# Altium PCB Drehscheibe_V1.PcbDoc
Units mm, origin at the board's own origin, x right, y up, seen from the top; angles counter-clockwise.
Board outline 100 x 80 mm, 2 copper layers (Top Layer, Bottom Layer); 75 components, 66 nets, 301 pads, 41 vias.
Unrouted connection lines stored in the file: 1.
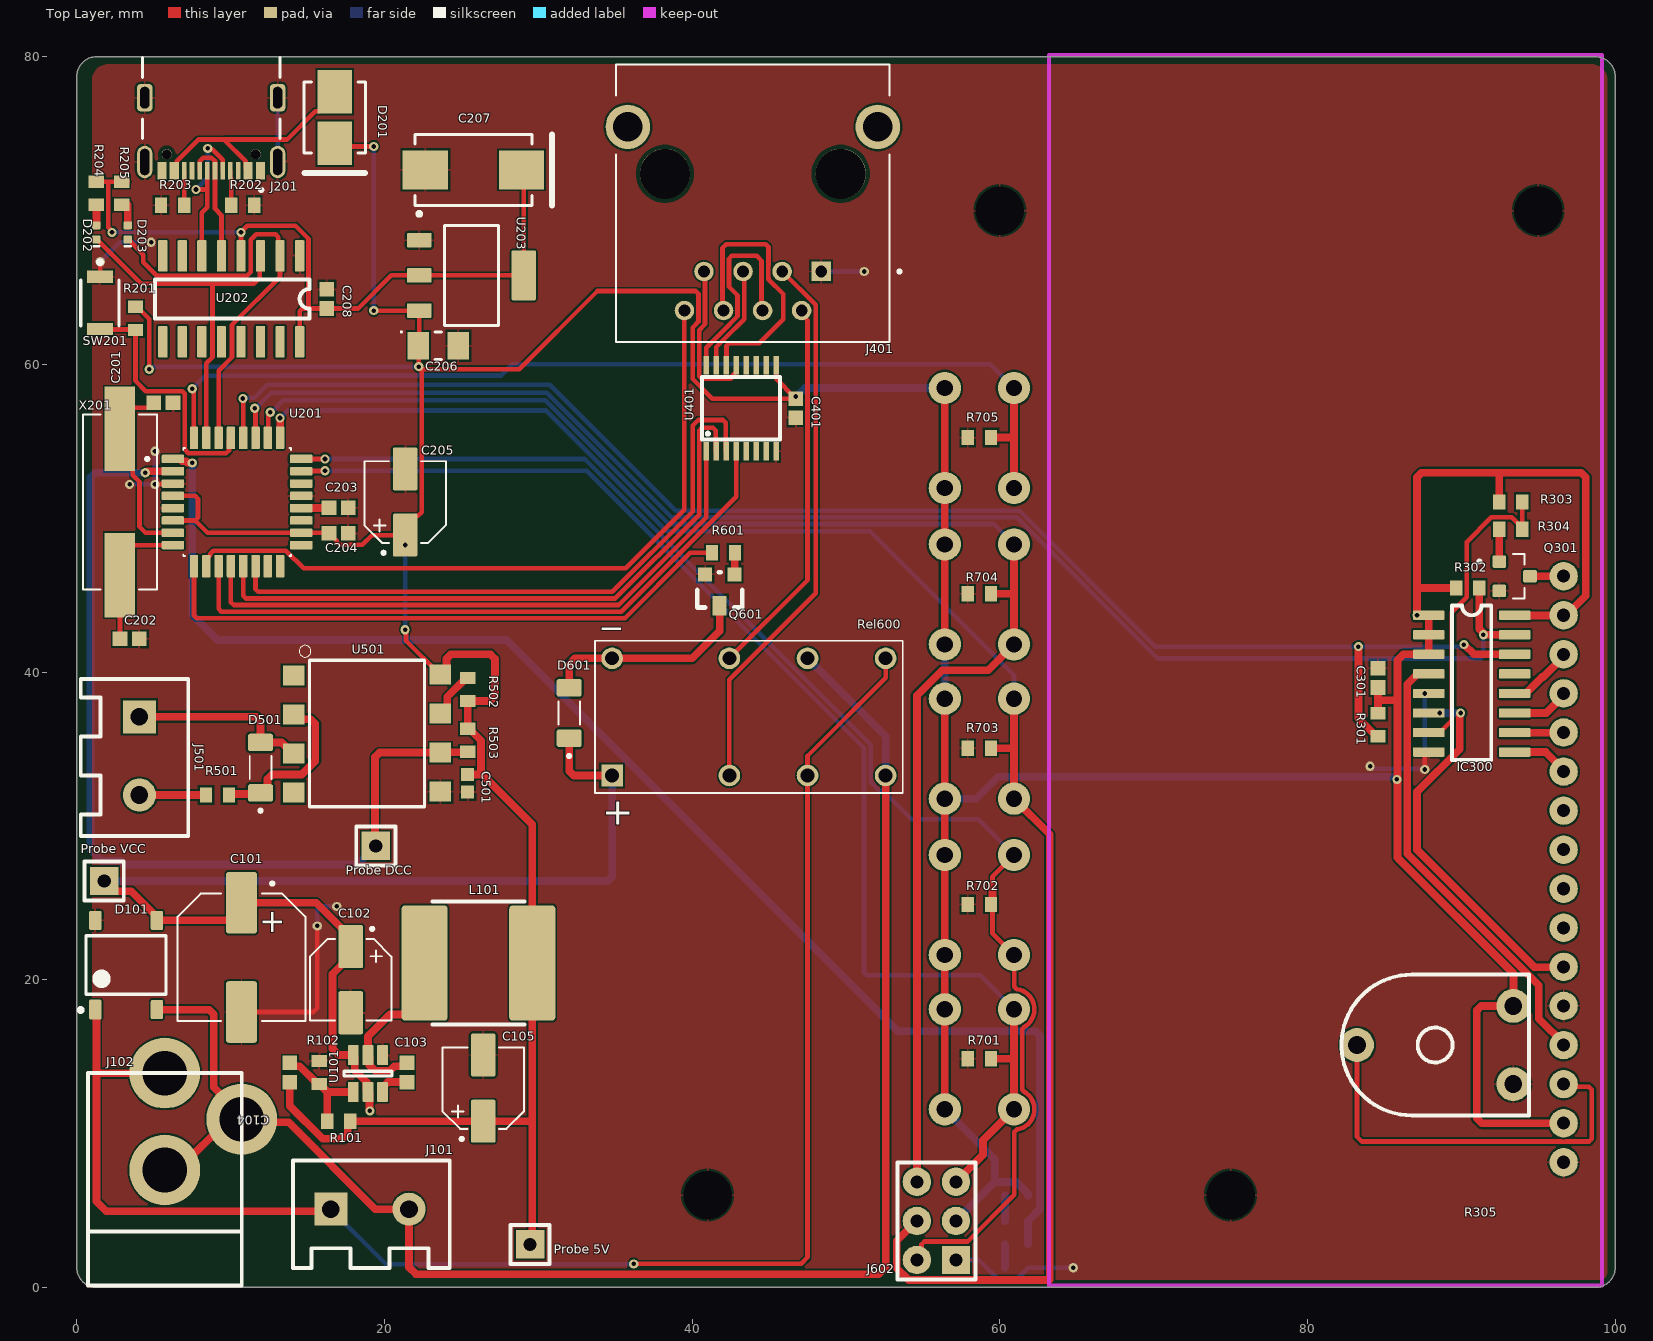
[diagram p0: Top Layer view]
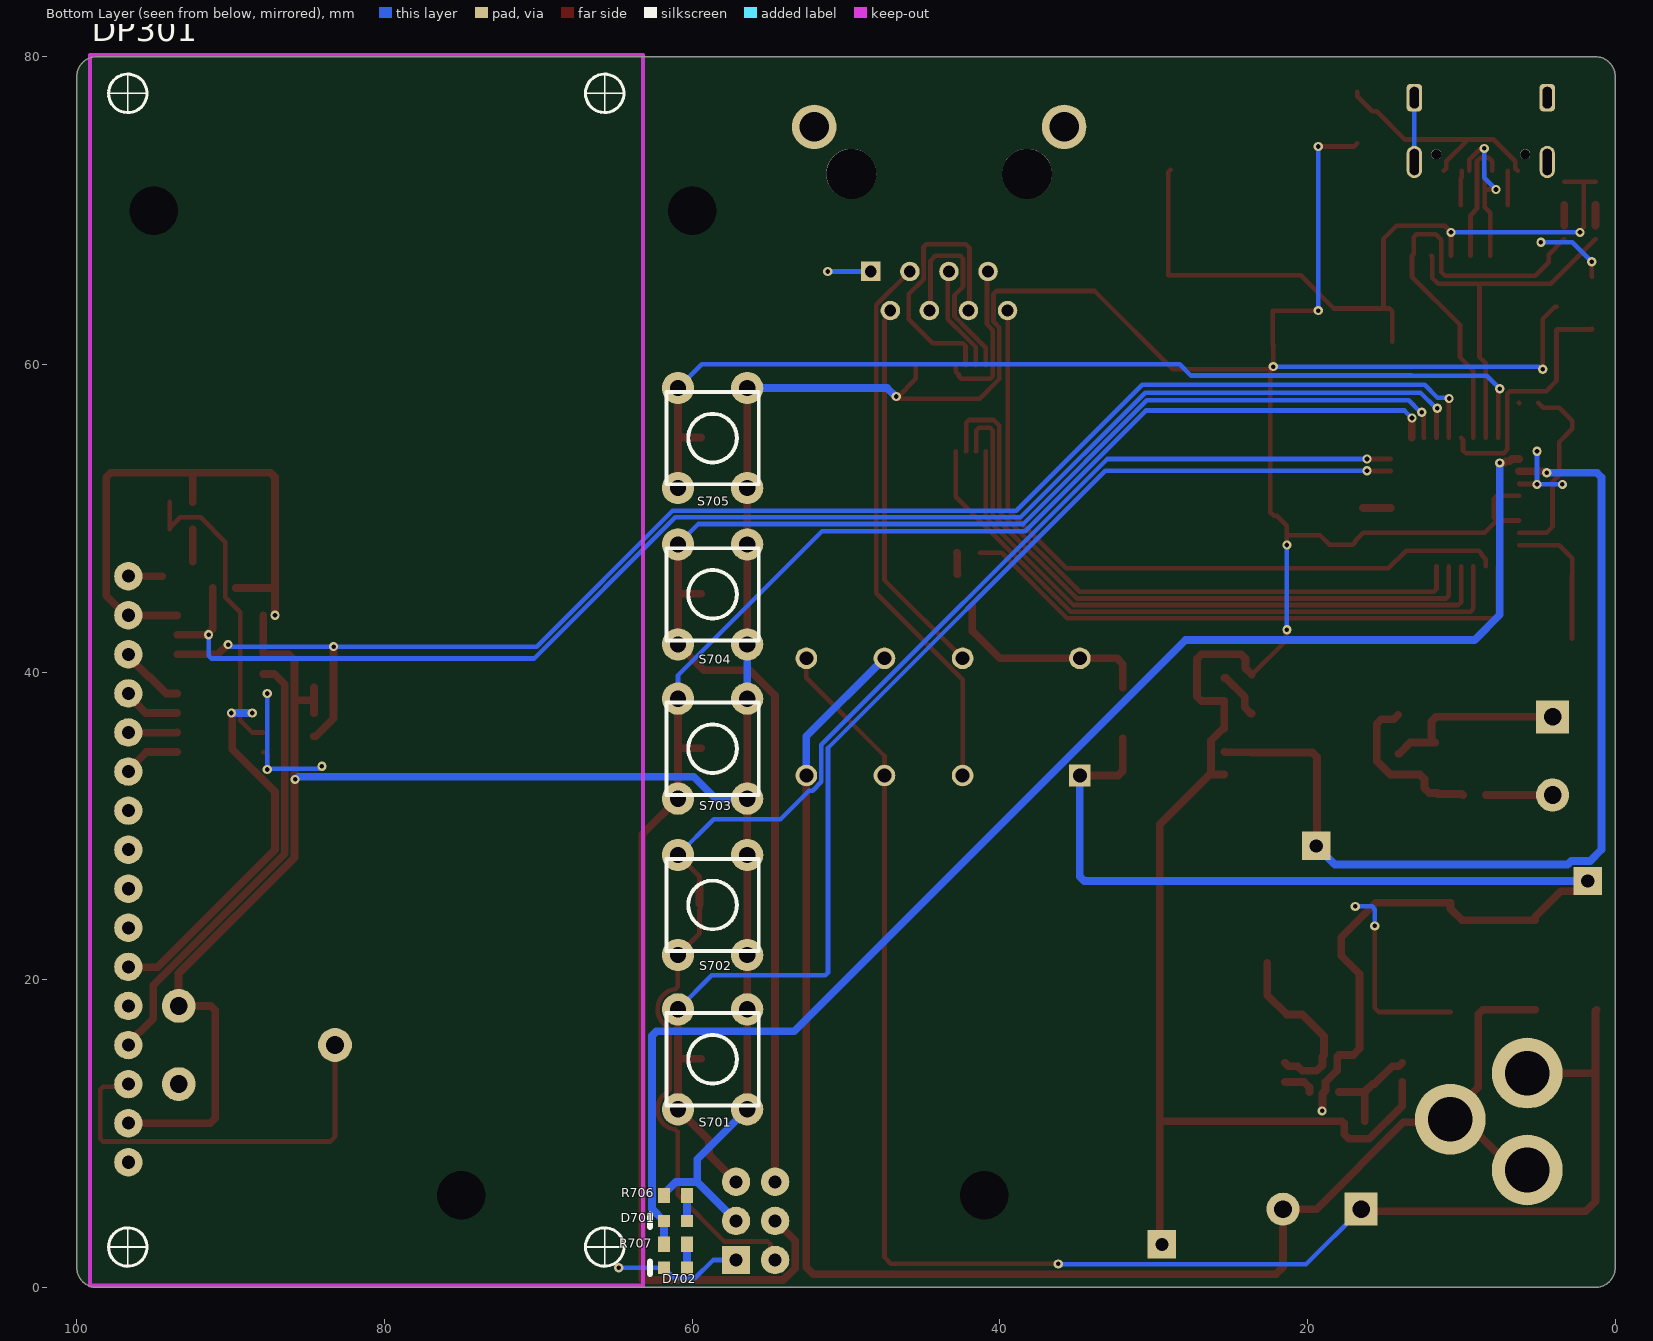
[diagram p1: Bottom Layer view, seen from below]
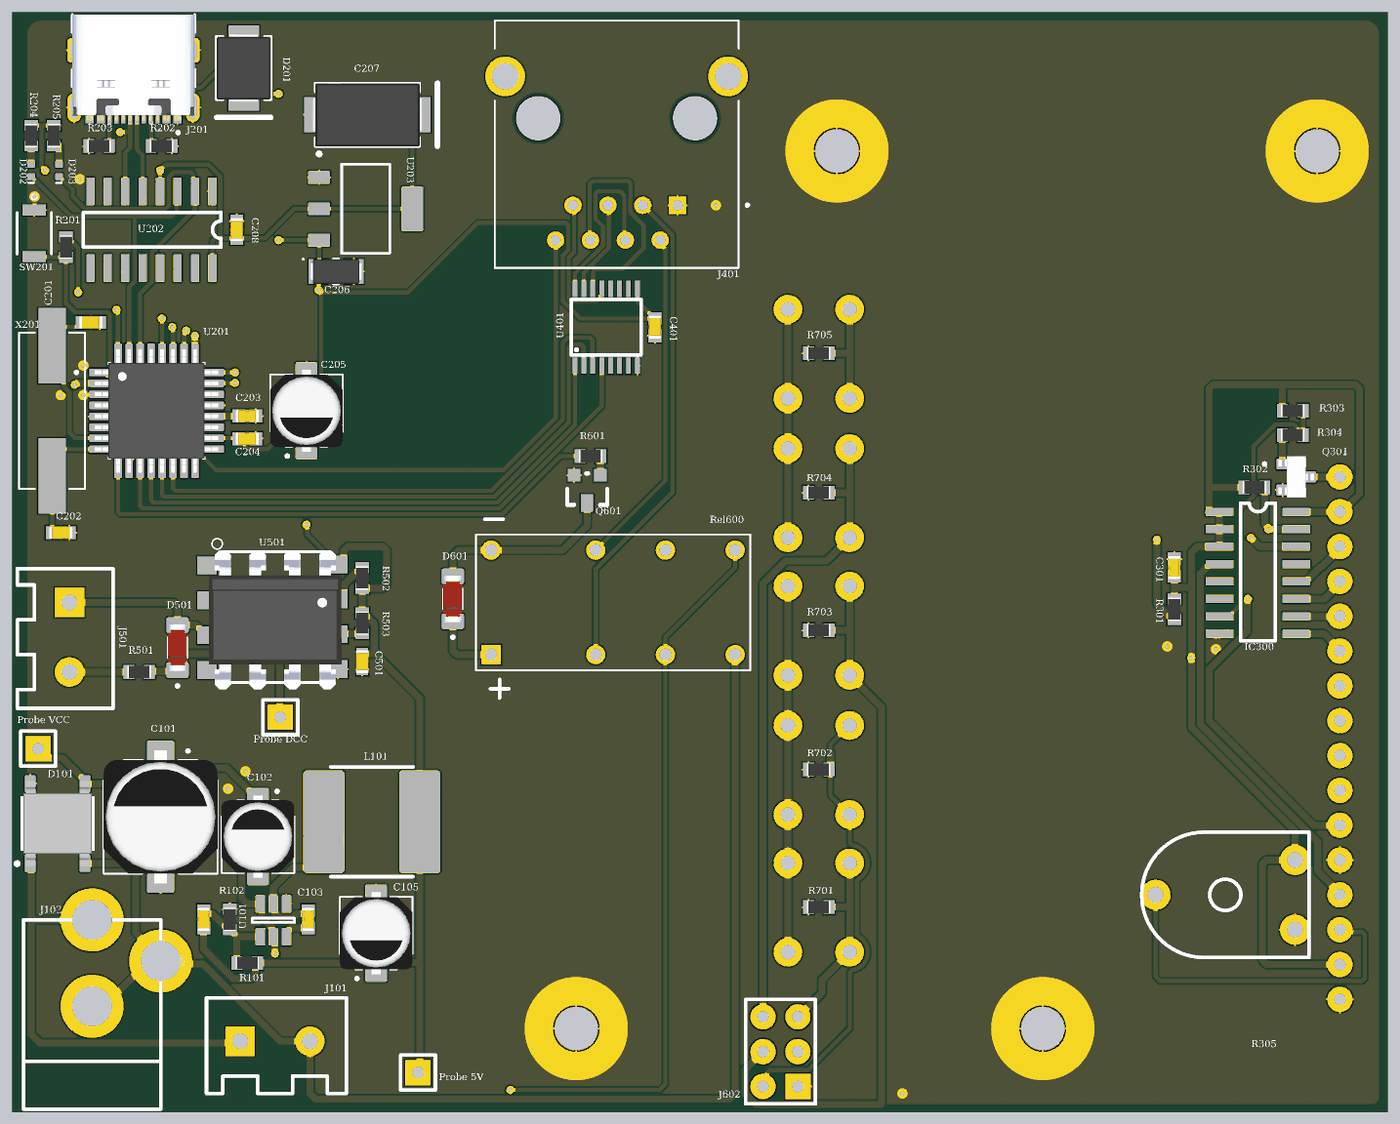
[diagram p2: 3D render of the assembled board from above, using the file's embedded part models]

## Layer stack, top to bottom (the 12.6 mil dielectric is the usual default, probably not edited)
Top Solder: solder mask 0.0102, Solder Resist, Dk 3.5
Top Layer: signal copper 0.0356
Dielectric 1: dielectric 0.32, FR-4, Dk 4.8
Bottom Layer: signal copper 0.0356
Bottom Solder: solder mask 0.0102, Solder Resist, Dk 3.5

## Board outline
0,1.27 0,78.73 cw(c1.27,78.73) 1.27,80 98.73,80 cw(c98.73,78.73) 100,78.73 100,1.27 cw(c98.73,1.27) 98.73,0 1.27,0 cw(c1.27,1.27)

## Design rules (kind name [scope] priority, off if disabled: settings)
BoardOutlineClearance [All] p1: gap=0.2 ignorepadtopadclearanceinfootprint=FALSE
Clearance [All] p1: gap=0.127 ignorepadtopadclearanceinfootprint=FALSE except(0.25: Arc-Hole Track-Hole SMDPad-Hole THPad-Hole Via-Hole Fill-Hole Poly-Hole Region-Hole Text-Hole)
ComponentClearance [All] p1: gap=0.127 collisioncheckmode=3 verticalgap=0.127 showdistances=TRUE
DiffPairsRouting [All] p1: maxlimit=0.254 minlimit=0.127 mostfreqgap=0.127 toplayer_minwidth=0.127 toplayer_maxwidth=25.4 toplayer_prefwidth=0.127 bottomlayer_minwidth=0.127 bottomlayer_maxwidth=25.4 bottomlayer_prefwidth=0.127 maxuncoupledlength=12.7
Height [All] p1: minheight=0 maxheight=1816.048 prefheight=12.7
HoleSize [All] p1: absolutevalues=TRUE maxlimit=6.3 minlimit=0.3 maxpercent=80.000 minpercent=20.000
HoleToHoleClearance [All] p1: gap=0.25 allowstackedmicrovias=FALSE
MinimumAnnularRing [All] p1: minimumring=0.076
MinimumSolderMaskSliver [All] p1: minsoldermaskwidth=0
PlaneClearance [All] p1: clearance=0.127
PlaneConnect PlaneConnectPowerPads [InPadClass('PowerPads')] p1: planeconnectstyle=Direct reliefexpansion=0.508 reliefentries=4 reliefconductorwidth=0.254 reliefairgap=0.254
PlaneConnect [All] p2: pad.planeconnectstyle=Relief pad.reliefexpansion=0.3 pad.reliefentries=4 pad.reliefconductorwidth=0.127 pad.reliefairgap=0.127 via.planeconnectstyle=Direct via.reliefexpansion=0.3 via.reliefentries=4 via.reliefconductorwidth=0.127 via.reliefairgap=0.127
PolygonConnect PolygonConnectPowerPads [All vs (InPadClass('PowerPads'))] p1: connectstyle=Direct reliefconductorwidth=0.254 reliefentries=4 polygonreliefangle="90 Angle" airgapwidth=0.254
PolygonConnect [All] p2: thpad.connectstyle=Relief thpad.reliefconductorwidth=0.127 thpad.reliefentries=4 thpad.polygonreliefangle="90 Angle" thpad.airgapwidth=0.127 smdpad.connectstyle=Relief smdpad.reliefconductorwidth=0.127 smdpad.reliefentries=4 smdpad.polygonreliefangle="90 Angle" smdpad.airgapwidth=0.127 via.connectstyle=Direct via.reliefconductorwidth=0.127 via.reliefentries=4 via.polygonreliefangle="90 Angle" via.airgapwidth=0.127
RoutingVias [All] p1: holewidth=0.3 width=0.6 viastyle="Through Hole" minholewidth=0.3 minwidth=0.6 maxholewidth=0.6 maxwidth=6.6
SilkToSilkClearance [All] p1: silktosilkclearance=0
SilkToSolderMaskClearance [IsPad] p1: minsilkscreentomaskgap=0.127 clearancetoexposedcopper=TRUE
SolderMaskExpansion [All] p1: expansion=0.075 istentingtop=FALSE
Width [All] p1: maxlimit=25.4 minlimit=0.127 preferedwidth=0.127 minimp=50.000000 maximp=50.000000 favimp=50.000000
20 further rules are at their usual default settings.

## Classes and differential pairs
component class uC_V1: C201 C202 C203 C204 C205 C206 C207 C208 D201 D202 D203 J201 R201 R202 R203 R204 R205 SW201 U201 U202 U203 X201
component class Stepper_V1: C401 J401 U401
component class "Relais und Connector_V1": D601 J602 Q601 R601 Rel600
component class PSU_V1: C101 C102 C103 C104 C105 D101 J101 J102 L101 "Probe 5V" "Probe VCC" R101 R102 U101
component class Display_V1: C301 DP301 IC300 Q301 R301 R302 R303 R304 R305
component class Demudulation_V1: C501 D501 J501 "Probe DCC" R501 R502 R503 U501
component class Bediehneinheit_V1: D701 D702 R701 R702 R703 R704 R705 R706 R707 S701 S702 S703 S704 S705

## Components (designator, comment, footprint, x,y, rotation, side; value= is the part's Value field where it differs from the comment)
C101 "470uf" C_SMD_F-TYP 10.7,21.45 r270 top
C102 "10uf" C_SMD_C-TYP 17.8,20 r270 top
C103 "Capacitor 100 nF +/-10% 50 V 0603" CAPC1608X90X40NL10T20 21.463,13.97 r90 top value=100nF
C104 "22pF" CAPC1608X90X40NL10T20 13.843,13.97 r270 top
C105 "22uf" C_SMD_C-TYP 26.416,12.954 r90 top
C201 "22pF" CAPC1608X90X40NL10T20 5.625,57.5 r180 top
C202 "22pF" CAPC1608X90X40NL10T20 3.429,42.164 r180 top
C203 "100nF" CAPC1608X90X40NL10T20 17.018,50.673 r180 top
C204 "100nF" CAPC1608X90X40NL10T20 17.018,49.022 r180 top
C205 "10uf" C_SMD_C-TYP 21.336,51.054 r90 top
C206 "TAJA106K016RNJ" CAPMP3217X18-T_V 23.495,61.214 r0 top value=10µF
C207 "293D226X9020D2TE3" VISH-7343-31_M 25.781,72.644 r180 top value=22µF
C208 "Capacitor 100 nF +/-10% 50 V 0603" CAPC1608X90X40NL10T20 16.256,64.262 r270 top value=100nF
C301 "100nF" CAPC1608X90X40NL10T20 84.582,39.624 r270 top
C401 "Capacitor 100 nF +/-10% 50 V 0603" CAPC1608X90X40NL10T20 46.736,57.15 r90 top value=100nF
C501 "Capacitor 1 uF +/- 10% 25 V 0603" CAPC1608X90X40LL10T20 25.4,32.766 r90 top value=1µF
D101 "*3D Model may have slightly different dimensions" SO-DIL-ABS-4mm 3.2,20.955 r90 top
D201 "SS54B" JCET-SMB-2_M 16.764,76.049 r270 top
D202 "QBLP595-IB" QTB-QBLP595_V 1.27,68.58 r90 top
D203 "QBLP595-IB" QTB-QBLP595_V 3.302,68.58 r90 top
D501 "FDLL4148" DIOMELF3414N 11.938,33.782 r90 top
D601 "FDLL4148" DIOMELF3414N 32.004,37.338 r90 top
D701 "19-217/Y5C-AM1N1VY/3T" EVRL-0603-2_V 61.087,4.318 r0 bottom
D702 "19-217/Y5C-AM1N1VY/3T" EVRL-0603-2_V 61.087,1.27 r0 bottom
DP301 "LC-Display" V_THT_WM-C1610M 81.153,40.132 r90 bottom
IC300 "PCF8574" SO-16 87.884,43.688 r0 top
J101 "VIN" "J_THT_Printklemme 2x" 19.05,5.08 r0 top
J102 "DC-Buchse" J_THT_CJ-25 5.715,0.127 r90 top
J201 "USB4105GFA120" GCT_USB4105GFA120 8.732,77.34 r180 top
J401 "RJ45-8N-B" TE_RJ45-8N-B 43.942,72.39 r180 top
J501 "DCC" "J_THT_Printklemme 2x" 4.064,34.544 r270 top
J602 "CON 2x3" J_2x3 55.88,4.318 r90 top
L101 "6,8uH" L_SMD_NPIS42LS 29.106,21.082 r90 top
"Probe 5V" "#Wert" SIP-1 29.464,4.064 r90 top
"Probe DCC" "#Wert" SIP-1 19.431,29.972 r90 top
"Probe VCC" "#Wert" SIP-1 1.778,27.686 r90 top
Q301 "BC847B" TRANS_BC847B 93.472,46.228 r0 top
Q601 "BC848B" SOT-23 42.748,46.355 r180 top
R101 "40k2" RESC1608X55X25ML10T15 17.018,10.795 r0 top
R102 "7k68" RESC1608X55X25ML10T15 15.748,13.97 r270 top
R201 "10k" RESC1608X55X25ML10T15 3.81,62.992 r270 top
R202 "5k1" RESC1608X55X25ML10T15 10.783,70.358 r0 top
R203 "5k1" RESC1608X55X25ML10T15 6.223,70.358 r0 top
R204 "Resistor 1k +/-1% 0603 100 mW" RESC1608X55X25ML10T15 1.27,71.12 r90 top value=1k
R205 "Resistor 1k +/-1% 0603 100 mW" RESC1608X55X25ML10T15 2.921,71.12 r90 top value=1k
R301 "10k" RESC1608X55X25ML10T15 84.582,36.576 r270 top
R302 "10k" RESC1608X55X25ML10T15 90.424,45.466 r0 top
R303 "10k" RESC1608X55X25ML10T15 93.218,51.054 r0 top
R304 "Resistor 1k +/-1% 0603 100 mW" RESC1608X55X25ML10T15 93.218,49.276 r180 top value=1k
R305 "R-Trim" TP-.2/.4 93.381,13.214 r90 top
R501 "Resistor 1k +/-1% 0603 100 mW" RESC1608X55X25ML10T15 9.144,32.004 r0 top value=1k
R502 "Resistor 10k +/-1% 0603 100 mW" RESC1608X55X25ML10T15 25.4,38.862 r270 top value=10k
R503 "Resistor 10k +/-1% 0603 100 mW" RESC1608X55X25ML10T15 25.4,35.56 r90 top value=10k
R601 "Resistor 1k +/-1% 0603 100 mW" RESC1608X55X25ML10T15 42.037,47.752 r0 top value=1k
R701 "Resistor 10k +/-1% 0603 100 mW" RESC1608X55X25ML10T15 58.674,14.859 r0 top value=10k
R702 "Resistor 10k +/-1% 0603 100 mW" RESC1608X55X25ML10T15 58.674,24.892 r0 top value=10k
R703 "Resistor 10k +/-1% 0603 100 mW" RESC1608X55X25ML10T15 58.674,35.052 r0 top value=10k
R704 "Resistor 10k +/-1% 0603 100 mW" RESC1608X55X25ML10T15 58.674,45.085 r0 top value=10k
R705 "Resistor 10k +/-1% 0603 100 mW" RESC1608X55X25ML10T15 58.674,55.245 r0 top value=10k
R706 "470" RESC1608X55X25ML10T15 61.087,5.969 r0 bottom
R707 "470" RESC1608X55X25ML10T15 61.087,2.794 r0 bottom
Rel600 "DS2Y-S-DC12V" RELAY_DS2Y-S-DC12V 43.688,37.084 r0 top
S701 "Taster4Kl." S_THT_Taster4kl. 58.674,14.824 r90 bottom
S702 "Taster4Kl." S_THT_Taster4kl. 58.674,24.857 r90 bottom
S703 "Taster4Kl." S_THT_Taster4kl. 58.674,35.017 r90 bottom
S704 "Taster4Kl." S_THT_Taster4kl. 58.674,45.05 r90 bottom
S705 "Taster4Kl." S_THT_Taster4kl. 58.674,55.21 r90 bottom
SW201 "B3U-1000P" OMRON-B3U-1000_V 1.5,64 r270 top
U101 "DIO6970" SOT23-6 19.873,12.7 r270 top
U201 "ATMEGA328P-AU" QFP80P900X900X120-32N 10.414,51.054 r0 top
U202 "CH340" SO-16 14.478,67.056 r270 top
U203 "#Wert" U_SMD_AMS1117 25.654,65.786 r0 top
U401 "ULN2003A" TSSOP-16-TI 43.18,57.15 r90 top
U501 "6N137S" 8-SMD 19.05,35.814 r270 top
X201 "16MHz" X_SMD_XTAL 2.794,51.054 r270 top

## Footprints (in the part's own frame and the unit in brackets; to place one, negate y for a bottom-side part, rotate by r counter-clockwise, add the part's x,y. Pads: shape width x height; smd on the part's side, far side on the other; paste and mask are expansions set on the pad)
8-SMD [mm]
  rect 1.3x1.4 smd: 1(-3.96,-4.96) 2(-1.42,-4.96) 3(1.12,-4.96) 4(3.66,-4.96) 5(3.59,4.58) 6(1.05,4.58) 7(-1.49,4.58) 8(-4.03,4.58)
  silkscreen extent -5.92,-4.6 4.57,3.56, body extent -5.08,-4.84 5.08,4.84, height 4.6
C_SMD_C-TYP [mm] "LB-2024-04-15"
  rrect15% 2.8x1.6 smd paste-0.02 mask+0.05: 1(-2.15,0) 2(2.15,0)
  silkscreen extent -3.4,-2.65 2.65,2.65, body extent 0,0 0,0
C_SMD_F-TYP [mm] "LB-2024-04-16"
  rrect15% 4x2 smd paste-0.02 mask+0.05: 1(-3.55,0) 2(3.55,0)
  silkscreen extent -4.9,-4.15 4.15,4.15, body extent 0,0 0,0
CAPC1608X90X40LL10T20 [mm] "Chip Capacitor, 2-Leads, Body 1.70x0.90mm, IPC High Density"
  rect 0.85x0.85 smd: 1(-0.575,0) 2(0.575,0)
  body extent -0.85,-0.45 0.85,0.45, height 0.9
CAPC1608X90X40NL10T20 [mm] "Chip Capacitor, 2-Leads, Body 1.70x0.90mm, IPC Medium Density"
  rect 0.95x0.95 smd: 1(-0.625,0) 2(0.625,0)
  body extent -0.85,-0.45 0.85,0.45, height 0.9
CAPMP3217X18-T_V [mm] "Molded Capacitor, 2-Leads, Body 3.40x1.8mm"
  rect 1.4x1.8 smd: 1(-1.3,0) 2(1.3,0)
  silkscreen extent -2.45,-0.9 0.2,0.95, body extent -1.92,-0.9 1.92,0.9, height 1.8
DIOMELF3414N [mm]
  rrect25% 1.14x1.63 smd: A(1.64,0) C(-1.64,0)
  silkscreen extent -2.89,-0.7 0.75,0.7, body extent -1.7,-0.7 1.7,0.7, height 1.4
EVRL-0603-2_V [mm] "SMD, 2-Leads, Body 1.6x0.8mm"
  rect 0.8x0.8 smd: 1(-0.75,0) 2(0.75,0)
  silkscreen extent 1.65,-0.4 1.65,0.4, body extent -0.8,-0.4 0.8,0.4, height 0.5
GCT_USB4105GFA120 [mm]
  rect 0.6x1.15 smd: A1_B12(-3.2,4.755) A4_B9(-2.4,4.755) B1_A12(3.2,4.755) B4_A9(2.4,4.755)
  rect 0.3x1.15 smd: A5(-1.25,4.755) A6(-0.25,4.755) A7(0.25,4.755) A8(1.25,4.755) B5(1.75,4.755) B6(0.75,4.755) B7(-0.75,4.755) B8(-1.75,4.755)
  oval 1x2.1 hole 0.6 slot 1.7 at 90 deg: SH1(-4.32,4.18) SH2(4.32,4.18)
  rrect50% 1x1.8 hole 0.6 slot 1.4 at 90 deg: SH3(-4.32,0) SH4(4.32,0)
  round 0.65 hole 0.65 unplated: ""(-2.89,3.68) ""(2.89,3.68)
  silkscreen extent -4.47,-2.6 4.47,6.1, body extent -4.47,-2.6 4.47,5.11, height 3.31
J_2x3 [mm] "LB-2024-04-19"
  rect 1.85x1.85 hole 0.85 mask+0.102: 1(-2.54,-1.27)
  round 1.85 hole 0.85 mask+0.102: 2(-2.54,1.27) 3(0,-1.27) 4(0,1.27) 5(2.54,-1.27) 6(2.54,1.27)
  silkscreen extent -3.81,-2.54 3.81,2.54
J_THT_CJ-25 [mm] "LB-2024-04-19"
  round 4.6 hole 2.9: 1(13.8,0) 2(7.5,0) 3(10.8,-5)
  silkscreen extent 0,-5 13.8,5
"J_THT_Printklemme 2x" [mm] "LB-2024-04-17"
  rect 2.15x2.15 hole 1.15: 1(-2.54,0)
  round 2.15 hole 1.15: 2(2.54,0)
  silkscreen extent -5,-3.81 5.19,3.17
JCET-SMB-2_M [mm] "Molded Diode, 2-Leads, Body 4.57x3.94mm"
  rect 2.85x2.25 smd: 1(-1.675,0) 2(1.675,0)
  silkscreen extent -2.3,-2 3.6,2, body extent -2.5,-1.97 2.5,1.97, height 2.44
L_SMD_NPIS42LS [mm] "LB-2024-04-17"
  rrect15% 7.5x3 smd paste-0.02 mask+0.05: 1(0,-0.5) 2(0,6.5)
  silkscreen extent -4,0 4,6
OMRON-B3U-1000_V [mm] "SMD, 2-Leads, Body 3x2.5mm"
  rect 0.8x1.7 smd: 1(-1.7,0) 2(1.7,0)
  silkscreen extent -2.77,-1.25 1.5,1.25, body extent -1.5,-1.25 1.5,1.25, height 1.75
QFP80P900X900X120-32N [mm]
  rrect25% 1.47x0.55 smd paste+0 mask+0.102: 1(-4.17,2.8) 2(-4.17,2) 3(-4.17,1.2) 4(-4.17,0.4) 5(-4.17,-0.4) 6(-4.17,-1.2) 7(-4.17,-2) 8(-4.17,-2.8) 17(4.17,-2.8) 18(4.17,-2) 19(4.17,-1.2) 20(4.17,-0.4) 21(4.17,0.4) 22(4.17,1.2) 23(4.17,2) 24(4.17,2.8)
  rrect25% 0.55x1.47 smd paste+0 mask+0.102: 9(-2.8,-4.17) 10(-2,-4.17) 11(-1.2,-4.17) 12(-0.4,-4.17) 13(0.4,-4.17) 14(1.2,-4.17) 15(2,-4.17) 16(2.8,-4.17) 25(2.8,4.17) 26(2,4.17) 27(1.2,4.17) 28(0.4,4.17) 29(-0.4,4.17) 30(-1.2,4.17) 31(-2,4.17) 32(-2.8,4.17)
  silkscreen extent -5.94,-3.5 3.5,3.5, body extent -4.5,-4.5 4.5,4.5, height 1.2
QTB-QBLP595_V [mm] "SMD, 2-Leads, Body 1x0.5mm"
  rrect25% 0.5x0.55 smd: 1(-0.455,0) 2(0.455,0)
  silkscreen extent -0.9,-0.2 -0.9,0.2, body extent -0.5,-0.25 0.5,0.25, height 0.5
RELAY_DS2Y-S-DC12V [mm]
  rect 1.408x1.408 hole 0.9: 1(-8.89,-3.81)
  round 1.408 hole 0.9: 4(-1.27,-3.81) 6(3.81,-3.81) 8(8.89,-3.81) 9(8.89,3.81) 11(3.81,3.81) 13(-1.27,3.81) 16(-8.89,3.81)
  silkscreen extent -10,-4.95 10,4.95
RESC1608X55X25ML10T15 [mm] "Chip Resistor, 2-Leads, Body 1.70x0.90mm, IPC Low Density"
  rect 0.8x1 smd: 1(-0.75,0) 2(0.75,0)
  body extent -0.85,-0.45 0.85,0.45, height 0.55
S_THT_Taster4kl. [mm] "LB-2024-04-17"
  round 2.1 hole 1.05: 1(-3.25,2.25) 1(3.25,2.25) 2(-3.25,-2.25) 2(3.25,-2.25)
  silkscreen extent -3,-3 3,3
SIP-1 [mm] "LB-2024-04-17"
  rect 1.85x1.85 hole 0.85: 1(-1.27,0)
  silkscreen extent -2.54,-1.27 0,1.27
SO-16 [mil] "LB-2024-04-17"
  rrect15% 80x24 smd paste-0.79 mask+1.97: 1(0,0) 2(0,-50) 3(0,-100) 4(0,-150) 5(0,-200) 6(0,-250) 7(0,-300) 8(0,-350) 9(220,-350) 10(220,-300) 11(220,-250) 12(220,-200) 13(220,-150) 14(220,-100) 15(220,-50) 16(220,0)
  silkscreen extent 60,-370 160,25
SO-DIL-ABS-4mm [mm]
  rrect25% 1.3x0.8 smd: 1(-2.9,2)
  rrect25% 1.25x0.8 smd: 2(-2.9,-2) 3(2.9,-2) 4(2.9,2)
  silkscreen extent -3.05,-2.6 1.9,3.07, body extent -3.1,-2.47 3.09,2.48, height 1.5
SOT23-6 [mm] "LB-2024-04-25"
  rrect15% 1.3x0.7 smd paste-0.02 mask+0.05: 1(-2.4,0) 2(-2.4,-0.95) 3(-2.4,-1.9) 4(0,-1.9) 5(0,-0.95) 6(0,0)
  silkscreen extent -1.35,-2.5 -1.05,0.6
SOT-23 [mil]
  rect 36x36 smd: 1(0,0) 2(75,0)
  rect 36x50 smd: 3(38,80)
  silkscreen extent -20,-5 95,85
TE_RJ45-8N-B [mm]
  rect 1.268x1.268 hole 0.76: 1(-4.445,6.35)
  round 1.268 hole 0.76: 2(-3.175,8.89) 3(-1.905,6.35) 4(-0.635,8.89) 5(0.635,6.35) 6(1.905,8.89) 7(3.175,6.35) 8(4.445,8.89)
  round 2.895 hole 1.93: 9(-8.125,-3.05) 10(8.125,-3.05)
  round 3.25 hole 3.25 unplated: ""(-5.715,0) ""(5.715,0)
  silkscreen extent -9.63,-7.11 8.89,10.92
TP-.2/.4 [mm] "Trimpotentiometer liegend klein"
  round 2.2 hole 1.15: 1(0,0) 2(5.08,0) 3(2.54,10.16)
  silkscreen extent -2.03,-1.02 7.11,11.17
TRANS_BC847B [mm]
  rrect25% 0.9x0.8 smd paste+0 mask+0.102: 1(-1,0.95) 2(-1,-0.95) 3(1,0)
  silkscreen extent -2.4,-1.45 0.65,1.45, body extent -1.3,-1.52 1.3,1.52, height 1.3
TSSOP-16-TI [mm]
  rect 1.2x0.35 smd paste+0 mask+0: 1(-2.808,2.275) 2(-2.808,1.625) 3(-2.808,0.975) 4(-2.808,0.325) 5(-2.808,-0.325) 6(-2.808,-0.975) 7(-2.808,-1.625) 8(-2.808,-2.275) 9(2.795,-2.275) 10(2.795,-1.625) 11(2.795,-0.975) 12(2.795,-0.325) 13(2.795,0.325) 14(2.795,0.975) 15(2.795,1.625) 16(2.795,2.275)
  silkscreen extent -2.03,-2.54 2.03,2.54
U_SMD_AMS1117 [mm] "LB-2024-04-17"
  rrect15% 1.604x0.952 smd paste-0.02 mask+0.05: 1(-3.395,2.29) 2(-3.395,0) 3(-3.395,-2.29)
  rrect15% 1.604x3.262 smd paste-0.02 mask+0.05: 2(3.395,0)
  silkscreen extent -3.52,-3.25 1.75,4.12
V_THT_WM-C1610M [mm] "LB-2024-04-19"
  round 1.85 hole 0.85: 1(-32,15.5) 2(-29.46,15.5) 3(-26.92,15.5) 4(-24.38,15.5) 5(-21.84,15.5) 6(-19.3,15.5) 7(-16.76,15.5) 8(-14.22,15.5) 9(-11.68,15.5) 10(-9.14,15.5) 11(-6.6,15.5) 12(-4.06,15.5) 13(-1.52,15.5) 14(1.02,15.5) 15(3.56,15.5) 16(6.1,15.5)
  Keep-Out Layer lines w0.254: -40,-17.962 -40,18 39.99,18 39.99,-17.962 -40,-17.962
  silkscreen extent -38.76,-16.75 38.74,16.79
VISH-7343-31_M [mm] "Molded Capacitor, 2-Leads, Body 7.6x4.6mm, IPC Low Density"
  rect 2.95x2.55 smd: 1(-3.125,0) 2(3.125,0)
  silkscreen extent -5.1,-2.3 3.8,2.3, body extent -4.02,-2.3 4.02,2.3, height 3.1
X_SMD_XTAL [mm] "LB-2024-04-17"
  rect 5.5x2 smd: 1(-4.75,0) 2(4.75,0)
  silkscreen extent -5.7,-2.4 5.7,2.4

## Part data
C101 C102 C105 C205: library part C_SMD_ELK, "SMD Elektrolytkondensator"
C103 C104 C201 C202 C203 C204 C208 C301 C401: library part CMP-001-00017-6, "Chip Capacitor, 100 nF, +/- 10%, 50 V, 0603 (1608 Metric)", Capacitor Type=Ceramic, Case/Package=0603, Max Operating Temperature=125°C, Min Operating Temperature=-55°C, Tolerance=10%, Voltage Rating=50V
C206: library part CMP-001-00041-7, "Standard Tantalum, 10 uF, +/- 10%, 16 V, -55 to 125 degC, 1206 (3216 Metric), RoHS, Tape and Reel", Capacitor Type=Tantalum, Case/Package=1206, Manufacturer=AVX, Max Operating Temperature=125°C, Min Operating Temperature=-55°C, Package Description="2-Pin Surface Mount Device, Body 3.2 x 1.65 mm", Package Quantity=1, Package Reference=CAPMP3217X18-T, Tolerance=10%, Voltage Rating=16V
C207: library part CMP-001-00021-7, "Solid Tantalum Chip Capacitor, 22 uF, +/- 10%, 20 V, -55 to 125 degC, 2917 (7343 Metric), RoHS, Tape and Reel", Capacitor Type=Tantalum, Case/Package=7343-31, Manufacturer="Vishay Semiconductor", Max Operating Temperature=125°C, Min Operating Temperature=-55°C, Package Description="2-Pin Surface Mount Device, Body 7.3 x 4.3 mm", Tolerance=10%, Voltage Rating=20V
C501: library part CMP-001-00005-6, "Chip Capacitor, 1 uF, +/- 10%, 25 V, 0603 (1608 Metric)", Capacitor Type=Ceramic, Case/Package=0603, Max Operating Temperature=125°C, Min Operating Temperature=-55°C, Tolerance=10%, Voltage Rating=25V
D101: library part Bridge_1ph
D201: library part CMP-004-00006-2, "Schottky Barrier Rectifier, 40 V, 5 A, -55 to 150 degC, 2-Pin SMD", Case/Package=SMB-2, Manufacturer=JCET, Package Description="2-Pin Surface Mount Device, Body 4.315 x 3.62 mm"
D202 D203: library part CMP-007-00042-3, "Chip LED 0402, Blue, 0.02 A, 3.1 to 3.7 V, -40 to 80 degC, 2-Pin SMD, RoHS, Tape and Reel", Case/Package=0402, Colour=Blue
D501 D601: "Diode Standard 100 V 200mA Surface Mount SOD-80", Package="SOD-80-2 ON Semiconductor"
D701 D702: library part CMP-007-00005-2, "Chip LED, Yellow, 5 V, 25mA, -40 to 85 degC, 2-Pin SMD (0603), RoHS, Tape and Reel", Case/Package=0603, Manufacturer="Everlight Electronics", Package Description="2-Pin Surface Mount Device, Body 1.6 x 0.8 mm"
DP301: library part "V_THT_LCD Modul", "LCD"
IC300: library part IC_PCF8574, "I/O Expander"
J101 J501: library part "J_THT_Printklemme 2x", "Printklemme"
J102: library part J_THT_Hohlstecker
J201: "USB CONN, 2.0 TYPE C, RCPT, 16POS, SMT; USB Connector Type:USB Type C; USB Standard:USB 2.0; Gender:Receptacle; No. of Positions:16Positions; Connector Mounting:Surface Mount, Through Hole Mount; Orientation:Right Angle RoHS Compliant: Yes", Package=None
J401: "RJ Jack / Signal Line EMI/RFI Filters 6 TERM LOW PROFILE BLOCK INDUCTOR 8 PIN", Package=None
J602: library part "J_THT_IDC 2x3", "Stecker"
L101: library part L_SMD_Spule, "Spule SMD"
"Probe 5V" "Probe DCC" "Probe VCC": library part J_THT_CON1, "Stecker"
Q301: "BJT, SOT-23, 45V, 100mA, NPN, 0.25W, 150Â°C", Package="SOT-23 Diotec"
Q601: library part Q_SMD_NPN, "NPN Transistor"
R101 R102 R201 R202 R203 R301 R302 R303 R502 R503 R701 R702 R703 R704 R705 R706 R707: library part CMP-009-00017-5, "Chip Resistor, 10 KOhm, +/- 1%, 01 W, -55 to 155 degC, 0603 (1608 Metric)", Case/Package=0603, Max Operating Temperature=155°C, Min Operating Temperature=-55°C, Power=100mW, Tolerance=1%, Voltage Rating=50V
R204 R205 R304 R501 R601: library part CMP-009-00014-5, "Chip Resistor, 1 KOhm, +/-1%, 0.1 W, -55 to 155 degC, 0603 (1608 Metric)", Case/Package=0603, Max Operating Temperature=155°C, Min Operating Temperature=-55°C, Power=100mW, Tolerance=1%, Voltage Rating=50V
R305: "Potentiometer"
Rel600: "General Purpose Relay DPDT _2 Form C_ Through Hole", Package="DIP-20 NXP Semiconductors"
S701 S702 S703 S704 S705: library part S_THT_Taster, "Taster"
SW201: library part CMP-011-00000-2, "Tactile Switch, SPST-NO, 0.05 A, 12 V, -25 to 70 degC, 2-Pin SMD, RoHS, Tape and Reel", Case/Package=B3U-1000, Contact Current Rating=50mA, IP Rating=IP40, Manufacturer="Omron Electronic Components", Max Contact Resistance=100mohm, Max Operating Temperature=70°C, Max Voltage Rating (DC)=12V, Min Operating Temperature=-25°C, Operating Force=153gf, Package Description="2-Pin Surface Mount Device, Body 3 x 2.5 mm", Package Quantity=3500, Resistance=0.1Ohm
U101: library part U_DIO6970, "Buckconverter"
U201: "MICROCONTROLLER MCU, 8 BIT, ATMEGA, 20MH; MICROCONTROLLER MCU, 8 BIT, ATMEGA, 20MHZ, TQFP-32; Controller Family/Series:ATmega; CPU Speed:20MHz; Program Memory Size:32KB; RAM Memory Size:2KB; No. of Pins:32Pins; MCU Case Style:TQFP; No. of I/O's:23I/O's; P", Package=None
U202: library part IC_CH340, "UART"
U203: library part U_SMD_AMS1117, "Linearwandler", Dropout Voltage=1.1V, Manufacturer="Advanced Monolithic Systems", Manufacturer Part Number=AMS1117-3.3, Max Junction Temp=+125°C, Max Power Dissipation=1.2W, Max Supply Voltage=15V, Nominal Supply Current=5mA, Output Current=1A, Output Voltage=3.3V, Package=AMS1117, Temperature="-40°C to +125°C", Temperature Range Low=-40°C
U401: "DARLINGTON ARRAY 7NPN, 2003, DIP16; Transistor Polarity:NPN; Collector Emitter Voltage V(br)ceo:50V; DC Collector Current:500mA; DC Current Gain hFE:1000; Operating Temperature Range:-20Â°C to +85Â°C; Transistor Case Style:DIP; No. of Pins:16; SVHC:No SVH", Package="DIP-16 Sprague"
U501: "Logic Output Optoisolator 15MBd Open Collector 5000Vrms 1 Channel 10kV/µs CMTI 8-SMD", Package="SMD-8 Lite-On Inc."
X201: library part X_SMD_Quarz, "Quarz SMD"

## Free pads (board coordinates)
  round 1.524 hole 3.15 paste+3 mask+3: 12(41,6) 12(60,70) 12(75,6) 12(95,70)

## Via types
v1: diameter 0.6, hole 0.3, Top Layer to Bottom Layer, 41 vias

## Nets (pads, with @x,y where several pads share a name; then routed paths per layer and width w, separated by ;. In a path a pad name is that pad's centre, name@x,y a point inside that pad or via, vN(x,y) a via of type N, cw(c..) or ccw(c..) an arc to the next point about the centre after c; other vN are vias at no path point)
+3V3: C207.1 C208.2 R204.2 R205.2 U202.4 U202.16 U203.2 | length 49.2
  Top Layer w0.3: R204.2 2.032,71.87 ; v1(2.286,68.58) 2.286,68.652 2.032,68.906 2.032,69.84 2.047,69.855 2.047,70.885 2.032,70.9 2.032,71.87 ; R205.2@3.302,71.87 2.032,71.87 ; U202.4 v1(10.668,68.58) 10.668,68.6 11.075,69.007 14.213,69.007 15.06,68.16 15.06,63.637 ; U202.16 14.478,63.461 14.654,63.637 15.06,63.637 ; C207.1 29.049,72.501 29.049,65.786 22.259,65.786 20.429,65.786 18.28,63.637 C208.2 15.06,63.637
  Bottom Layer w0.3: v1(2.286,68.58) v1(10.668,68.58)
+5V: "Probe 5V.1" C104.2 C105.1 C204.2 C205.1 C206.1 C301.2 C401.2 C501.2 D201.2 DP301.2 DP301.15 IC300.1 IC300.2 IC300.3 IC300.16 J602.3 L101.1 R101.2 R201.1 R301.1 R302.1 R303.1 R305.2 R502.2 R503.2 R706.2 S701.2 S702.2 S703.2 S704.2 S705.2 U201.4 U201.6 U201.18 U203.3 U401.9 U501.8 | length 369.9
  Top Layer w0.3: R201.1 3.91,63.742 4.699,62.953 v1(4.699,59.69) ; U201.6 7.69,49.854 ; U201.4 7.698,51.454 7.874,51.278 7.874,50.038 7.69,49.854 ; D201.2 16.97,74.168 v1(19.304,74.168) ; v1(19.304,63.5) 19.306,63.498 22.257,63.498 U203.3 22.259,61.278 C206.1 22.225,61.184 v1@22.225,59.69 ; v1(21.336,42.757) 21.393,42.7 21.393,42.031 23.58,39.844 U501.8 ; v1(21.336,48.26) C205.1 ; v1@22.413,59.688 28.761,59.688 33.843,64.77 40.232,64.77 40.408,64.594 40.408,62.78 40.026,62.398 40.026,59.054 41.305,57.775 C401.2 ; v1@22.413,59.69 22.413,50.391 22.176,50.154 21.986,50.154 21.336,49.504 C205.1 ; U401.9 45.455,59.056 C401.2@46.667,57.844 ; 7.69,49.854 8.49,49.054 U201.18 16.361,49.054 C204.2 16.891,48.524 16.891,48.432 17.053,48.27 18.553,48.27 19.187,48.904 C205.1
  Top Layer w0.5: C104.2 13.843,11.787 15.978,9.652 17.325,9.652 17.618,9.945 17.618,10.645 R101.2 26.407,10.795 C105.1 29.313,10.804 ; U501.8 24.03,40.244 24.03,40.855 24.322,41.148 26.885,41.148 27.178,40.855 27.178,38.405 26.885,38.112 R502.2 R503.2 25.5,36.31 26.277,35.533 26.277,33.341 C501.2 ; 26.354,33.341 29.606,30.089 L101.1 29.606,2.936 29.464,2.794 ; S701.2@56.11,11.574 56.424,11.574 56.424,18.074 56.424,21.607 56.424,28.107 56.424,31.767 S703.2@56.424,38.267 ; S704.2@56.424,41.8 56.424,48.3 56.424,51.96 S705.2@56.424,58.46 ; R301.1 84.582,38.163 ; C301.2 84.582,38.163 ; v1(87.122,43.688) 87.122,45.339 ; IC300.1 IC300.2 IC300.3 86.243,41.148 85.852,40.757 85.852,38.1 ; R302.1 87.249,45.466 87.122,45.339 ; R303.1 92.468,52.825 92.602,52.959 ; R305.2 91.294,18.294 91,18 91,11 91.328,10.672 DP301.2 ; R305.2@93.392,18.294 93.392,20.4 85.852,27.94 85.852,38.1 ; IC300.16 93.481,43.679 96.771,43.679 96.78,43.67 98.082,44.972 98.082,52.666 97.789,52.959 92.602,52.959 ; 84.582,38.163 85.789,38.163 85.852,38.1 ; 87.122,45.339 87.122,52.666 87.415,52.959 92.602,52.959
  Bottom Layer w0.3: v1(4.699,59.69) 4.78,59.69 4.948,59.858 v1(22.225,59.858) ; v1(19.304,63.5) v1(19.304,74.168) ; v1(21.336,42.757) v1(21.336,48.26)
  Bottom Layer w0.5: v1(46.736,57.912) 46.763,57.912 47.311,58.46 S705.2@56.424,58.46 ; S701.2@56.424,11.574 59.678,8.32 59.678,6.846 ; S703.2@56.424,31.767 58.473,31.767 59.9,33.194 85.613,33.194 85.787,33.02 v1(85.814,33.02) ; S703.2@56.424,38.267 S704.2@56.424,41.8 ; J602.3 59.678,6.846 ; R706.2 61.837,6.069 61.06,6.846 59.678,6.846
ADC6: U201.19
ADC7: U201.22
BL: IC300.7 R303.2 R304.1 | length 20.2
  Top Layer w0.3: IC300.7 88.595,36.068 89.377,36.85 89.377,43.877 90.352,44.852 90.352,48.451 91.953,50.053 93.291,50.053 R304.1@93.968,49.376 ; R304.1 R304.1@93.968,49.376 ; R303.2 R304.1@93.968,49.376
D4: DP301.11 IC300.9 | length 3.8
  Top Layer w0.5: IC300.9 95.492,34.798 DP301.11@96.78,33.51
D5: DP301.12 IC300.10 | length 3.3
  Top Layer w0.5: IC300.10 93.481,36.059 96.771,36.059 DP301.12@96.78,36.05
D6: DP301.13 IC300.11 | length 3.8
  Top Layer w0.5: IC300.11 95.528,37.338 DP301.13@96.78,38.59
D7: DP301.14 IC300.12 | length 4.4
  Top Layer w0.5: IC300.12 94.183,38.608 95.251,39.676 95.326,39.676 DP301.14@96.78,41.13
D+: J201.A6 J201.B6 U202.5 | length 8.1
  Top Layer w0.3: J201.B6 7.982,73.202 8.217,73.437 8.747,73.437 8.982,73.202 J201.A6 8.982,70.117 9.398,69.701 U202.5
D-: J201.A7 J201.B7 U202.6 | length 11.4
  Top Layer w0.3: v1(7.747,71.374) 8.454,71.374 8.482,71.402 ; U202.6 8.128,69.864 8.482,70.218 8.482,71.402 ; J201.A7 8.482,71.402 ; v1(8.509,74.041) 8.566,73.984 8.804,73.984 9.482,73.306 J201.B7
  Bottom Layer w0.3: v1(7.747,71.374) 8.509,72.136 v1(8.509,74.041)
DCC: "Probe DCC.1" R503.1 U201.2 U501.6 | length 61.2
  Top Layer w0.5: v1(4.445,52.959) 4.472,52.959 4.567,53.054 U201.2 ; 19.38,28.651 19.38,34.471 19.673,34.764 U501.6 23.653,34.787 25.377,34.787 R503.1
  Bottom Layer w0.5: v1(4.445,52.959) 1.182,52.959 0.889,52.666 0.889,28.448 1.619,27.718 2.859,27.718 3.09,27.487 18.216,27.487 19.431,28.702
EN: DP301.6 IC300.6 | length 24.2
  Top Layer w0.5: v1(89.954,37.338) 89.954,37.311 89.904,37.261 89.904,34.991 87.122,32.209 87.122,28.448 94.76,20.81 DP301.6@96.78,20.81
  Bottom Layer w0.5: v1(88.6,37.338) v1(89.954,37.338)
ESS: J401.8 U201.10 | length 46.8
  Top Layer w0.3: U201.10 8.414,47.344 8.662,47.592 8.662,47.693 8.865,47.896 13.581,47.896 14.741,46.736 35.687,46.736 39.497,50.546 J401.8
FRST: R705.2 S705.1 U201.32 | length 66
  Top Layer w0.3: v1(7.493,58.42) 7.493,58.339 7.596,58.235 7.596,55.241 U201.32
  Top Layer w0.5: R705.2 60.889,55.245 60.924,55.21 ; S705.1@60.924,51.96 60.924,55.21 ; S705.1@60.924,58.46 60.924,55.21
  Bottom Layer w0.3: v1(7.493,58.42) 8.336,59.263 13.21,59.263 13.228,59.281 27.58,59.281 28.299,60 59.384,60 S705.1@60.924,58.46
GND: C101.2 C102.2 C105.2 C201.1 C202.1 C203.1 C204.1 C205.2 C206.2 C207.2 C208.1 C301.1 C401.1 C501.1 D101.4 D702.2 DP301.1 DP301.5 IC300.5 IC300.8 J201.A1_B12 J201.B1_A12 J201.SH1 J201.SH2 J201.SH3 J201.SH4 J401.1 J602.1 pad.12 Q301.2 Q601.2 R102.1 R202.2 R203.1 R305.1 R701.1 R702.1 R703.1 R704.1 R705.1 SW201.1 U101.1 U201.3 U201.5 U201.21 U202.1 U203.1 U401.8 U501.5 | length 47.9
  Top Layer w0.3: SW201.1 1.524,65.724 v1(1.524,66.675) ; v1(5.08,52.197) 5.108,52.225 6.215,52.225 U201.3 ; C201.1@6.223,57.473 C201.1 ; C101.2 15.36,17.9 15.621,18.161 v1(15.621,23.495) ; v1(87.62,33.665) 87.62,34.643 87.775,34.798 IC300.8
  Bottom Layer w0.3: v1(1.524,66.675) 2.794,67.945 v1(4.826,67.945) ; v1(3.429,52.197) v1(5.08,52.197) v1(5.08,54.356) ; J201.SH1 J201.SH3 ; v1(15.621,23.495) 15.621,24.589 15.797,24.765 v1(16.891,24.765) ; J401.1 v1(51.181,66.04) ; J602.1 58.637,1.778 59.822,0.593 61.16,0.593 D702.2 v1(64.77,1.27) ; v1(84.074,33.871) 84.155,33.871 84.305,33.721 87.564,33.721 v1(87.62,33.665) 87.625,33.669 87.625,38.603 v1(87.63,38.608)
GND-Diff: J401.2 Rel600.13 | length 24.9
  Top Layer w0.3: Rel600.13 47.498,45.974 47.498,62.857 47.117,63.238 J401.2
LED: D701.2 R707.2 U201.1 | length 91.6
  Top Layer w0.5: U201.1 6.704,53.854 6.852,53.706 7.095,53.706 7.188,53.613 7.474,53.613 v1(7.493,53.594)
  Bottom Layer w0.5: v1(7.493,53.594) 7.493,43.727 9.14,42.08 27.933,42.08 53.366,16.647 62.321,16.647 62.614,16.354 62.614,5.095 D701.2 R707.2
M1: J401.4 U401.16 | length 13.6
  Top Layer w0.3: U401.16 40.905,61.085 42.052,62.232 42.057,62.232 42.948,63.123 42.948,64.494 42.396,65.046 42.396,66.88 42.572,67.056 44.196,67.056 44.509,66.743 44.509,63.568 J401.4
M2: J401.5 U401.15 | length 6.9
  Top Layer w0.3: U401.15 41.555,61.131 42.229,61.805 42.234,61.805 43.375,62.946 43.375,65.972 J401.5
M3: J401.6 U401.14 | length 18.1
  Top Layer w0.3: J401.6 41.969,63.568 41.969,67.574 42.213,67.818 44.782,67.818 44.958,67.642 44.958,66.439 44.936,66.417 44.936,65.663 44.958,65.641 44.958,65.532 45.915,64.575 45.915,62.946 44.347,61.378 42.406,61.378 42.23,61.202 42.23,59.97 U401.14
M4: J401.7 U401.13 | length 10.1
  Top Layer w0.3: J401.7 40.835,65.972 40.835,62.603 40.453,62.221 40.453,59.231 40.615,59.068 42.495,59.068 42.657,59.231 42.657,59.322 42.855,59.52 U401.13
MISO: U201.16
MOSI: U201.15
NetC103_1: C103.1 U101.6 | length 2
  Top Layer w0.5: U101.6 19.873,13 20.218,13.345 C103.1
NetC103_2: C103.2 L101.2 U101.2 | length 11.6
  Top Layer w0.5: C103.2 21.238,14.37 20.645,14.37 20.348,14.073 19.398,14.073 19.023,14.448 19.023,15 U101.2 18.923,16.31 20.356,17.743 21.356,17.743 22.606,18.993 L101.2
NetC104_1: C104.1 R101.1 R102.2 U101.4 | length 7.2
  Top Layer w0.5: C104.1 14.068,14.37 14.498,14.37 15.648,13.22 R102.2 15.987,12.981 16.268,12.7 R101.1 ; R102.2@15.998,12.993 16.291,12.7 U101.4
NetC201_2: C201.2 U201.7 X201.1 | length 12.4
  Top Layer w0.3: C201.2 4.675,57.175 3.644,57.175 2.794,56.325 X201.1 3.644,54.954 3.644,52.798 4.068,52.374 4.068,49.447 4.462,49.054 U201.7
NetC202_2: C202.2 U201.8 X201.2 | length 9
  Top Layer w0.3: C202.2 2.804,46.294 X201.2 2.794,47.404 3.644,48.254 U201.8
NetC203_2: C203.2 U201.20 | length 1.8
  Top Layer w0.5: U201.20 14.593,50.664 16.384,50.664 C203.2
NetD201_1: D201.1 J201.A4_B9 J201.B4_A9 | length 15.7
  Top Layer w0.3: J201.B4_A9 6.482,72.735 6.482,73.202 7.898,74.618 9.566,74.618 ; J201.A4_B9 10.982,72.735 10.982,73.202 9.566,74.618 ; D201.1 16.764,77.424 15.789,76.449 15.489,76.449 13.658,74.618 9.566,74.618
NetD202_2: D202.2 R204.1 | length 1.3
  Top Layer w0.5: D202.2 R204.1
NetD203_2: D203.2 R205.1 | length 1.3
  Top Layer w0.5: D203.2 R205.1@3.302,70.37
NetD501_A: D501.A J501.1 U501.3 | length 12.1
  Top Layer w0.5: J501.1 11.645,37.084 11.938,36.791 D501.A ; D501.A@11.693,35.422 13.312,35.422 14.04,34.694 U501.3
NetD501_C: D501.C R501.2 U501.2 | length 11.3
  Top Layer w0.5: R501.2 9.963,32.073 D501.C@11.546,32.073 ; D501.C 11.546,32.142 12.076,32.142 12.396,32.462 12.396,33.047 12.689,33.339 14.619,33.339 15.494,34.215 15.494,36.642 15.201,36.934 14.39,36.934 U501.2
NetD601_A: D601.A Q601.3 Rel600.16 | length 13.9
  Top Layer w0.5: D601.A 32.004,40.513 32.385,40.894 Rel600.16 40.005,40.894 41.783,42.672 Q601.3
NetD701_1: D701.1 R706.1 | length 1.7
  Bottom Layer w0.5: D701.1 R706.1
NetD702_1: D702.1 R707.1 | length 1.5
  Bottom Layer w0.5: D702.1 R707.1
NetDP301_3: DP301.3 R305.3 | length 26.6
  Top Layer w0.3: R305.3 83.221,9.779 83.521,9.479 96.51,9.479 ccw(c96.653,10.672) 96.796,9.479 98.303,9.479 98.479,9.654 98.479,12.863 98.391,12.951 98.303,13.039 96.826,13.039 DP301.3
  Bottom Layer w0.5: DP301.3@96.771,13.199 DP301.3@96.78,13.19
NetDP301_16: DP301.16 Q301.3 | length 2.3
  Top Layer w0.5: Q301.3 94.481,46.219 96.771,46.219 DP301.16@96.78,46.21
NetJ201_A5: J201.A5 R202.1 | length 2.2
  Top Layer w0.3: J201.A5 9.982,72.16 10.033,72.109 R202.1
NetJ201_B5: J201.B5 R203.2 | length 2.2
  Top Layer w0.3: R203.2 6.973,72.151 6.982,72.16 J201.B5
NetJ501_2: J501.2 R501.1 | length 4.3
  Top Layer w0.5: J501.2 R501.1
NetQ301_1: Q301.1 R304.2 | length 2.1
  Top Layer w0.5: R304.2 92.47,49.274 92.47,47.18 Q301.1
NetQ601_1: Q601.1 R601.2 | length 1.4
  Top Layer w0.5: Q601.1 42.768,46.374 42.768,47.733 R601.2
NetR502_1: R502.1 U501.7 | length 3.1
  Top Layer w0.5: U501.7 23.68,37.304 24.08,37.704 24.08,38.392 25.3,39.612 R502.1
RS: DP301.4 IC300.4 | length 29.4
  Top Layer w0.5: IC300.4 87.173,39.878 86.491,39.196 86.491,28.19 95.039,19.642 95.039,17.471 DP301.4@96.78,15.73
RST: R201.2 SW201.2 U201.29 | length 16.7
  Top Layer w0.3: SW201.2 1.529,62.271 3.781,62.271 R201.2 3.81,58.93 4.488,58.252 6.84,58.252 7.002,58.09 7.002,56.498 7.002,54.475 7.248,54.229 7.265,54.212 9.696,54.212 9.889,54.405 9.889,55.099 U201.29
RX: D203.1 U201.30 U202.2 | length 28.2
  Top Layer w0.3: D203.1 3.327,68.125 4.311,67.141 4.311,66.647 5.195,65.763 11.061,65.763 11.303,66.005 11.303,68.107 11.649,68.453 12.923,68.453 13.099,68.277 13.099,67.165 U202.2 13.208,65.694 10.086,62.572 10.086,60.47 9.214,59.598 U201.30
SCK: U201.17
SCL: IC300.14 R301.2 U201.28 | length 99.4
  Top Layer w0.3: v1(10.795,57.785) 10.804,57.776 10.804,55.233 U201.28
  Top Layer w0.5: v1(83.312,41.656) 83.312,36.996 84.482,35.826 R301.2 ; v1(90.17,41.783) 90.197,41.783 90.832,41.148 IC300.14
  Bottom Layer w0.3: v1@10.797,57.785 10.844,57.832 11.545,57.832 12.387,58.674 30.734,58.674 38.927,50.481 61.279,50.481 70.104,41.656 v1(83.312,41.656) 89.962,41.656 90.089,41.783 v1(90.17,41.783)
SDA: IC300.15 R302.2 U201.27 | length 97.3
  Top Layer w0.3: v1(11.557,57.15) 11.557,57.123 11.614,57.066 U201.27
  Top Layer w0.5: R302.2 91.174,42.804 91.421,42.557 91.421,42.464 91.467,42.418 IC300.15@92.706,42.418 ; v1(91.44,42.418) IC300.15
  Bottom Layer w0.3: v1(11.557,57.15) 11.638,57.15 12.654,58.166 30.545,58.166 38.657,50.054 61.102,50.054 70.273,40.883 91.264,40.883 91.44,41.058 v1@91.44,42.391
SM1: U201.12 U401.1 | length 40
  Top Layer w0.3: U201.12 10.014,44.534 10.19,44.358 35.214,44.358 40.905,50.049 U401.1
SM2: U201.13 U401.2 | length 42
  Top Layer w0.3: U201.13 10.814,44.961 10.99,44.785 35.006,44.785 40.453,50.232 40.453,55.704 40.629,55.88 41.354,55.88 41.53,55.704 41.53,54.367 U401.2
SM3: U201.14 U401.3 | length 42
  Top Layer w0.3: U201.14 11.614,45.388 11.79,45.212 34.798,45.212 40.026,50.44 40.026,56.028 40.386,56.388 42.004,56.388 42.18,56.212 42.18,54.367 U401.3
SM4: U201.11 U401.4 | length 42.5
  Top Layer w0.3: U201.11 9.214,44.107 9.39,43.931 35.391,43.931 42.855,51.395 U401.4
T-180: J602.4 R703.2 S703.1 U201.25 | length 112
  Top Layer w0.5: v1(13.208,56.515) 13.211,56.512 13.211,55.227 U201.25 ; J602.4 53.308,3.016 53.308,1.239 54.071,0.476 63.187,0.476 63.219,0.508 63.246,0.508 63.246,29.445 60.924,31.767 60.924,35.017 ; R703.2 60.889,35.052 60.924,35.017 ; S703.1@60.924,38.267 60.924,35.017
  Bottom Layer w0.3: v1(13.208,56.515) 13.693,57 30.503,57 38.354,49.149 51.562,49.149 60.924,39.787 S703.1@60.924,38.267
T-+: J602.5 R701.2 S701.1 U201.23 | length 83.7
  Top Layer w0.3: U201.23 14.6,53.07 16.113,53.07 v1(16.129,53.086)
  Top Layer w0.5: J602.5 58.905,8.613 58.905,9.555 60.924,11.574 60.924,14.824 ; R701.2 60.889,14.859 60.924,14.824 ; S701.1@60.924,18.074 60.924,14.824
  Bottom Layer w0.3: v1(16.129,53.086) 33.147,53.086 51.17,35.063 51.17,20.458 51.348,20.28 58.718,20.28 S701.1@60.924,18.074
T--: J602.2 R702.2 S702.1 U201.24 | length 93.6
  Top Layer w0.3: U201.24 14.587,53.851 16.126,53.851 v1(16.129,53.848) ; J602.2 54.907,2.075 54.907,2.783 55.104,2.98 57.905,2.98 60.948,6.023 60.948,10.104 61.035,10.191 ; 59.521,26.284 59.521,26.704 S702.1@60.924,28.107 ; R702.2@59.642,24.892 59.642,26.162 59.486,26.319 59.424,26.257 R702.2 59.521,24.542 59.521,23.01 S702.1@60.924,21.607 ; S702.1@60.948,21.607 60.948,19.544 61.036,19.456 61.103,19.389 cw(c60.924,18.074) 61.567,16.913 61.539,16.885 ; 61.036,10.192 61.103,10.259 ccw(c60.924,11.574) 61.567,12.735 61.539,12.763 61.451,12.851 61.451,16.797 61.539,16.885
  Bottom Layer w0.3: v1(16.129,53.848) 33.02,53.848 51.597,35.271 51.597,32.868 52.172,32.293 52.406,32.293 54.259,30.44 58.591,30.44 S702.1@60.924,28.107
T-Play: J602.6 R704.2 S704.1 U201.26 | length 101.6
  Top Layer w0.3: U201.26 12.43,55.24 12.43,56.672 12.573,56.815 v1(12.573,56.896)
  Top Layer w0.5: J602.6 54.61,38.471 56.251,40.112 59.236,40.112 60.924,41.8 60.924,45.05 ; R704.2 60.889,45.085 60.924,45.05 ; S704.1@60.924,48.3 60.924,45.05
  Bottom Layer w0.3: v1(12.573,56.896) 12.654,56.896 13.416,57.658 30.449,57.658 38.48,49.627 59.597,49.627 S704.1@60.924,48.3
TX: D202.1 U201.31 U202.3 | length 23.6
  Top Layer w0.3: D202.1 1.295,68.125 4.184,65.236 8.816,65.236 ; U201.31 8.414,60.068 8.816,60.47 8.816,65.236 ; U202.3 11.883,67.001 11.883,65.616 11.503,65.236 8.816,65.236
VCC: "Probe VCC.1" C101.1 C102.1 D101.3 D601.C Rel600.1 U101.3 U101.5 | length 76.9
  Top Layer w0.5: 1.778,26.416 2.453,25.741 3.539,25.741 5.2,24.08 D101.3 9.95,23.855 10.7,24.605 C101.1 15.55,25 17.8,22.75 C102.1 17.8,21.55 16.623,20.373 16.623,15.503 17.026,15.1 U101.3 18.073,15 18.073,14.102 18.823,13.352 18.823,12.8 U101.5 19.023,12.6 19.023,11.526 19.05,11.499 v1(19.05,11.472) ; D601.C 32.004,33.567 32.297,33.274 Rel600.1
  Bottom Layer w0.5: 1.778,26.416 34.505,26.416 34.798,26.709 Rel600.1
VCC-Diff: J401.3 Rel600.4 | length 36
  Top Layer w0.3: Rel600.4 42.418,39.507 48.028,45.117 48.028,63.877 45.865,66.04 J401.3
VSSW: R601.1 U201.9 | length 38.7
  Top Layer w0.3: U201.9 7.614,43.68 7.79,43.504 35.63,43.504 39.878,47.752 R601.1
VW1: D101.2 J101.2 J102.2 J102.3 Rel600.8 Rel600.11 | length 107.9
  Top Layer w0.5: D101.2 8.597,18.055 8.89,17.762 8.89,13.001 10.715,11.176 J102.3 ; J102.2 6.565,7.627 9.865,10.927 J102.3 ; Rel600.8 52.578,1.309 52.116,0.847 22.052,0.847 21.59,1.309 J101.2 19.407,5.08 13.765,10.722 10.92,10.722 J102.3
  Bottom Layer w0.5: Rel600.11 52.578,35.814 Rel600.8
VW2: D101.1 J101.1 J102.1 Rel600.6 Rel600.9 | length 106.3
  Top Layer w0.3: v1(36.195,1.524) 47.078,1.524 47.498,1.944 Rel600.6 47.498,34.544 52.578,39.624 Rel600.9
  Top Layer w0.5: D101.1 1.27,17.985 1.27,14.15 ; J102.1 1.493,13.927 1.27,14.15 ; J101.1 16.38,4.95 1.908,4.95 1.27,5.588 1.27,14.15
  Bottom Layer w0.3: J101.1 20.098,1.492 36.136,1.492 36.168,1.524 v1(36.195,1.524)
pads on no net: DP301.7 DP301.8 DP301.9 DP301.10 IC300.13 J201. J201.A8 J201.B8 J401. J401.9 J401.10 U202.7 U202.8 U202.9 U202.10 U202.11 U202.12 U202.13 U202.14 U202.15 U401.5 U401.6 U401.7 U401.10 U401.11 U401.12 U501.1 U501.4

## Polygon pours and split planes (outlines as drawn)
GND on Top Layer "NONET_L01_P-001" (solid, remove dead copper, pour order 0): 99,0.5 ccw(c99,1) 99.5,1 99.5,78.5 ccw(c98.5,78.5) 98.5,79.5 2,79.5 ccw(c2,78.5) 1,78.5 1,1.5 ccw(c2,1.5) 2,0.5

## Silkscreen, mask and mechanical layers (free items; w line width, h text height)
Board Shape:
  lines w0.254: 0,1.27 ccw(c1.27,1.27) 1.27,0 98.73,0 ccw(c98.73,1.27) 100,1.27 100,78.73 ccw(c98.73,78.73) 98.73,80 1.27,80 ccw(c1.27,78.73) 0,78.73 0,2 0,1.27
